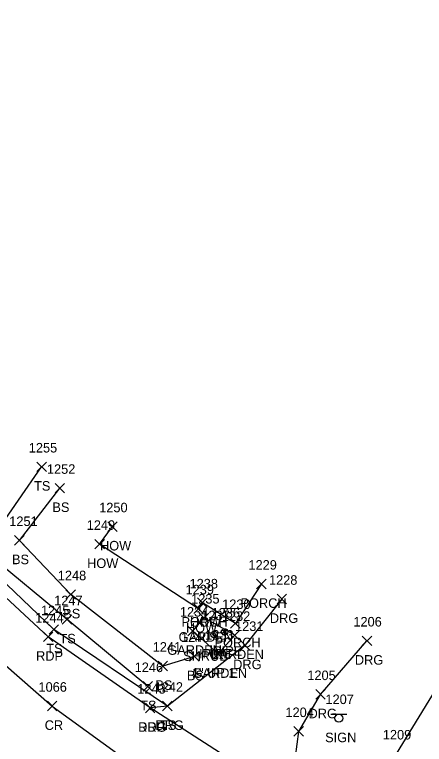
# Model space of a CAD drawing. Extents: x 1761340 to 1763889, y 696770 to 706023.
# Drawn here: x 1761478.8 to 1761564.7, y 700913.9 to 701066.9 of the extents above; entities that cross this region are included whole.
import ezdxf

# ---------------------------------------------------------------- set-up
doc = ezdxf.new("R2010")
doc.units = 0
for name, color, linetype in [('L_A', 7, 'Continuous'), ('L_C', 7, 'Continuous'), ('L_I', 7, 'Continuous'), ('L_TIC', 7, 'Continuous'), ('LAPB', 7, 'Continuous'), ('LBC', 7, 'Continuous'), ('LBF', 7, 'Continuous'), ('LELB', 7, 'Continuous'), ('M_A', 7, 'Continuous'), ('M_C', 7, 'Continuous'), ('M_I', 7, 'Continuous'), ('MPIP', 7, 'Continuous'), ('P_A', 7, 'Continuous'), ('P_I', 7, 'Continuous'), ('P_TIC', 7, 'Continuous'), ('PET', 7, 'Continuous'), ('PRC', 7, 'Continuous'), ('R_A', 7, 'Continuous'), ('R_I', 7, 'Continuous'), ('R_TIC', 7, 'Continuous'), ('RDG', 7, 'Continuous'), ('S_A', 7, 'Continuous'), ('S_I', 7, 'Continuous'), ('SSGN', 7, 'Continuous')]:
    doc.layers.add(name, color=color, linetype=linetype)

msp = doc.modelspace()

# ---------------------------------------------------------------- linework, layer by layer
at = {"layer": 'L_TIC'}
for points in [[(1761483.47, 700971.09), (1761485.47, 700973.09)], [(1761485.47, 700971.09), (1761483.47, 700973.09)], [(1761487.28, 700966.62), (1761489.28, 700968.62)], [(1761489.28, 700966.62), (1761487.28, 700968.62)], [(1761498.31, 700958.56), (1761500.31, 700960.56)], [(1761500.31, 700958.56), (1761498.31, 700960.56)], [(1761478.81, 700955.68), (1761480.81, 700957.68)], [(1761480.81, 700955.68), (1761478.81, 700957.68)], [(1761495.61, 700954.88), (1761497.61, 700956.88)], [(1761497.61, 700954.88), (1761495.61, 700956.88)], [(1761529.5, 700946.53), (1761531.5, 700948.53)], [(1761531.5, 700946.53), (1761529.5, 700948.53)], [(1761489.56, 700944.32), (1761491.56, 700946.32)], [(1761491.56, 700944.32), (1761489.56, 700946.32)], [(1761516.32, 700941.35), (1761518.32, 700943.35)], [(1761518.32, 700941.35), (1761516.32, 700943.35)], [(1761517.15, 700942.6), (1761519.15, 700944.6)], [(1761519.15, 700942.6), (1761517.15, 700944.6)], [(1761517.15, 700942.6), (1761519.15, 700944.6)], [(1761519.15, 700942.6), (1761517.15, 700944.6)], [(1761488.79, 700939.08), (1761490.79, 700941.08)], [(1761490.79, 700939.08), (1761488.79, 700941.08)], [(1761517.49, 700939.43), (1761519.49, 700941.43)], [(1761519.49, 700939.43), (1761517.49, 700941.43)], [(1761517.49, 700939.43), (1761519.49, 700941.43)], [(1761519.49, 700939.43), (1761517.49, 700941.43)], [(1761524.07, 700938.28), (1761526.07, 700940.28)], [(1761526.07, 700938.28), (1761524.07, 700940.28)], [(1761486.03, 700936.99), (1761488.03, 700938.99)], [(1761488.03, 700936.99), (1761486.03, 700938.99)], [(1761515.13, 700936.69), (1761517.13, 700938.69)], [(1761517.13, 700936.69), (1761515.13, 700938.69)], [(1761523.93, 700935.79), (1761525.93, 700937.79)], [(1761525.93, 700935.79), (1761523.93, 700937.79)], [(1761523.93, 700935.79), (1761525.93, 700937.79)], [(1761525.93, 700935.79), (1761523.93, 700937.79)], [(1761515.46, 700931.35), (1761517.46, 700933.35)], [(1761517.46, 700931.35), (1761515.46, 700933.35)], [(1761520.42, 700931.86), (1761522.42, 700933.86)], [(1761522.42, 700931.86), (1761520.42, 700933.86)], [(1761508.87, 700929.34), (1761510.87, 700931.34)], [(1761510.87, 700929.34), (1761508.87, 700931.34)], [(1761505.71, 700925.07), (1761507.71, 700927.07)], [(1761507.71, 700925.07), (1761505.71, 700927.07)], [(1761509.82, 700920.94), (1761511.82, 700922.94)], [(1761511.82, 700920.94), (1761509.82, 700922.94)]]:
    msp.add_lwpolyline(points, dxfattribs=at)
at = {"layer": 'LAPB'}
for points in [[(1761524.93, 700936.79), (1761521.42, 700932.86), (1761516.13, 700937.69), (1761518.49, 700940.43)], [(1761524.93, 700936.79), (1761518.49, 700940.43)]]:
    msp.add_lwpolyline(points, dxfattribs=at)
at = {"layer": 'LBC'}
msp.add_lwpolyline([(1761518.15, 700943.6), (1761517.32, 700942.35), (1761496.61, 700955.88), (1761499.31, 700959.56)], dxfattribs=at)
at = {"layer": 'LBF'}
msp.add_lwpolyline([(1761530.5, 700947.53), (1761525.07, 700939.28), (1761518.15, 700943.6)], dxfattribs=at)
at = {"layer": 'LELB'}
for points in [[(1761510.82, 700921.94), (1761487.03, 700937.99), (1761465.59, 700958.47), (1761457.07, 700967.17), (1761446.59, 700981.31), (1761437.01, 700994.98), (1761426.19, 701006.36), (1761420.48, 701017.58), (1761403.34, 701042.42), (1761383.02, 701066.87)], [(1761506.71, 700926.07), (1761489.79, 700940.08), (1761473.06, 700953.91), (1761474.72, 700958.12), (1761484.47, 700972.09)], [(1761516.46, 700932.35), (1761509.87, 700930.34), (1761490.56, 700945.32), (1761479.81, 700956.68), (1761488.28, 700967.62)], [(1761570.3, 700930.84), (1761558.73, 700911.94)]]:
    msp.add_lwpolyline(points, dxfattribs=at)
at = {"layer": 'MPIP'}
for points in [[(1761520.94, 700936.93), (1761520.6, 700937.27), (1761520.27, 700936.93), (1761520.6, 700936.6)], [(1761523.14, 700937.5), (1761522.8, 700937.84), (1761522.47, 700937.5), (1761522.8, 700937.17)]]:
    msp.add_lwpolyline(points, close=True, dxfattribs=at)
for centre in [(1761520.6, 700936.93), (1761522.8, 700937.5)]:
    msp.add_circle(centre, 0.667, dxfattribs=at)
at = {"layer": 'P_TIC'}
for points in [[(1761484.83, 700935.45), (1761486.83, 700937.45)], [(1761486.83, 700935.45), (1761484.83, 700937.45)], [(1761485.68, 700920.95), (1761487.68, 700922.95)], [(1761487.68, 700920.95), (1761485.68, 700922.95)], [(1761506.2, 700920.56), (1761508.2, 700922.56)], [(1761508.2, 700920.56), (1761506.2, 700922.56)]]:
    msp.add_lwpolyline(points, dxfattribs=at)
at = {"layer": 'PET'}
msp.add_lwpolyline([(1761565.69, 700887.32), (1761551.93, 700894.01), (1761537.2, 700902.21), (1761507.2, 700921.56), (1761485.83, 700936.45), (1761463.82, 700956.86), (1761451.66, 700968.66), (1761442.59, 700979.07), (1761431.29, 700993.83), (1761424.05, 701005.24), (1761416.58, 701016.18), (1761400.04, 701039.88), (1761381.47, 701065.28)], dxfattribs=at)
at = {"layer": 'PRC'}
msp.add_lwpolyline([(1761371.66, 701058.14), (1761390.63, 701031.26), (1761404.65, 701011.45), (1761424.14, 700986), (1761443.93, 700962.2), (1761463.21, 700942.49), (1761486.68, 700921.95), (1761508.06, 700906.42), (1761533.51, 700890.82), (1761557.04, 700878.89), (1761580.26, 700869.03), (1761600.69, 700862.06)], dxfattribs=at)
at = {"layer": 'R_TIC'}
for points in [[(1761533.79, 700943.37), (1761535.79, 700945.37)], [(1761535.79, 700943.37), (1761533.79, 700945.37)], [(1761526.11, 700933.68), (1761528.11, 700935.68)], [(1761528.11, 700933.68), (1761526.11, 700935.68)], [(1761551.61, 700934.62), (1761553.61, 700936.62)], [(1761553.61, 700934.62), (1761551.61, 700936.62)], [(1761541.9, 700923.39), (1761543.9, 700925.39)], [(1761543.9, 700923.39), (1761541.9, 700925.39)], [(1761506.2, 700920.56), (1761508.2, 700922.56)], [(1761508.2, 700920.56), (1761506.2, 700922.56)], [(1761509.82, 700920.94), (1761511.82, 700922.94)], [(1761511.82, 700920.94), (1761509.82, 700922.94)], [(1761537.32, 700915.64), (1761539.32, 700917.64)], [(1761539.32, 700915.64), (1761537.32, 700917.64)]]:
    msp.add_lwpolyline(points, dxfattribs=at)
at = {"layer": 'RDG'}
for points in [[(1761534.79, 700944.37), (1761527.11, 700934.68), (1761510.82, 700921.94), (1761507.2, 700921.56)], [(1761537.2, 700902.21), (1761536.94, 700905.99), (1761538.32, 700916.64), (1761542.9, 700924.39), (1761552.61, 700935.62)]]:
    msp.add_lwpolyline(points, dxfattribs=at)
at = {"layer": 'SSGN'}
for p, q in [((1761545.08, 700920.22), (1761548.41, 700920.22)), ((1761546.73, 700919.39), (1761546.73, 700919.39))]:
    msp.add_line(p, q, dxfattribs=at)
msp.add_circle((1761546.73, 700919.39), 0.833, dxfattribs=at)

# ---------------------------------------------------------------- texts
at = {"layer": 'L_A'}
for s, p in [('TS', (1761482.88, 700967.09)), ('BS', (1761486.72, 700962.62)), ('HOW', (1761496.7, 700954.56)), ('BS', (1761478.26, 700951.68)), ('HOW', (1761494, 700950.88)), ('PORCH', (1761526.13, 700942.53)), ('BS', (1761489, 700940.32)), ('PORCH', (1761513.77, 700938.6)), ('HOW', (1761515.53, 700938.6)), ('HOW', (1761514.7, 700937.35)), ('GARDEN', (1761513.16, 700935.43)), ('GARDEN', (1761513.16, 700935.43)), ('TS', (1761488.2, 700935.08)), ('PORCH', (1761520.69, 700934.28)), ('TS', (1761485.44, 700932.99)), ('GARDEN', (1761510.79, 700932.69)), ('GARDEN', (1761519.6, 700931.79)), ('GARDEN', (1761519.6, 700931.79)), ('GARDEN', (1761516.09, 700927.86)), ('BS', (1761514.9, 700927.35)), ('BS', (1761508.31, 700925.34)), ('TS', (1761505.12, 700921.07)), ('TS', (1761509.23, 700916.94))]:
    msp.add_text(s, height=2, dxfattribs=at).set_placement(p)
at = {"layer": 'L_C'}
msp.add_text('SHRUB', height=2, dxfattribs=at).set_placement((1761514.12, 700931.43))
msp.add_text('SHRUB', height=2, dxfattribs=at).set_placement((1761514.12, 700931.43))
at = {"layer": 'L_I'}
for s, p in [('1255', (1761481.78, 700975.09)), ('1252', (1761485.58, 700970.62)), ('1250', (1761496.53, 700962.56)), ('1251', (1761477.69, 700959.68)), ('1249', (1761493.91, 700958.88)), ('1229', (1761527.8, 700950.53)), ('1248', (1761487.86, 700948.32)), ('1238', (1761515.46, 700946.6)), ('1238', (1761515.46, 700946.6)), ('1239', (1761514.62, 700945.35)), ('1247', (1761487.1, 700943.08)), ('1235', (1761515.79, 700943.43)), ('1235', (1761515.79, 700943.43)), ('1230', (1761522.29, 700942.28)), ('1245', (1761484.33, 700940.99)), ('1234', (1761513.43, 700940.69)), ('1232', (1761522.23, 700939.79)), ('1232', (1761522.23, 700939.79)), ('1240', (1761513.68, 700935.35)), ('1233', (1761518.73, 700935.86)), ('1241', (1761507.74, 700933.34)), ('1246', (1761503.96, 700929.07)), ('1242', (1761508.13, 700924.94)), ('1209', (1761555.95, 700914.94)), ('1209', (1761555.95, 700914.94)), ('1209', (1761555.95, 700914.94))]:
    msp.add_text(s, height=2, dxfattribs=at).set_placement(p)
at = {"layer": 'M_A'}
for p in [(1761519.64, 700932.5), (1761517.44, 700931.93)]:
    msp.add_text('IPIPE', height=2, dxfattribs=at).set_placement(p)
at = {"layer": 'M_C'}
msp.add_text('1" UP 1\'', height=2, dxfattribs=at).set_placement((1761515.96, 700927.93))
at = {"layer": 'M_I'}
for s, p in [('1237', (1761517.91, 700939.93)), ('1236', (1761520.06, 700940.5))]:
    msp.add_text(s, height=2, dxfattribs=at).set_placement(p)
at = {"layer": 'P_A'}
for s, p in [('RDP', (1761483.31, 700931.45)), ('CR', (1761485.11, 700916.95)), ('RDP', (1761504.69, 700916.56))]:
    msp.add_text(s, height=2, dxfattribs=at).set_placement(p)
at = {"layer": 'P_I'}
for s, p in [('1244', (1761483.13, 700939.45)), ('1066', (1761483.81, 700924.95)), ('1243', (1761504.5, 700924.56))]:
    msp.add_text(s, height=2, dxfattribs=at).set_placement(p)
at = {"layer": 'R_A'}
for p in [(1761532.28, 700939.37), (1761550.09, 700930.62), (1761524.6, 700929.68), (1761540.39, 700919.39), (1761508.31, 700916.94), (1761504.69, 700916.56)]:
    msp.add_text('DRG', height=2, dxfattribs=at).set_placement(p)
at = {"layer": 'R_I'}
for s, p in [('1228', (1761532.1, 700947.37)), ('1206', (1761549.78, 700938.62)), ('1231', (1761524.99, 700937.68)), ('1205', (1761540.13, 700927.39)), ('1243', (1761504.5, 700924.56)), ('1242', (1761508.13, 700924.94)), ('1204', (1761535.55, 700919.64))]:
    msp.add_text(s, height=2, dxfattribs=at).set_placement(p)
at = {"layer": 'S_A'}
msp.add_text('SIGN', height=2, dxfattribs=at).set_placement((1761543.86, 700914.37))
at = {"layer": 'S_I'}
msp.add_text('1207', height=2, dxfattribs=at).set_placement((1761543.93, 700922.37))

doc.saveas('drawing.dxf')
